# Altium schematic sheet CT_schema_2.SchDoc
size 362 x 192 mm
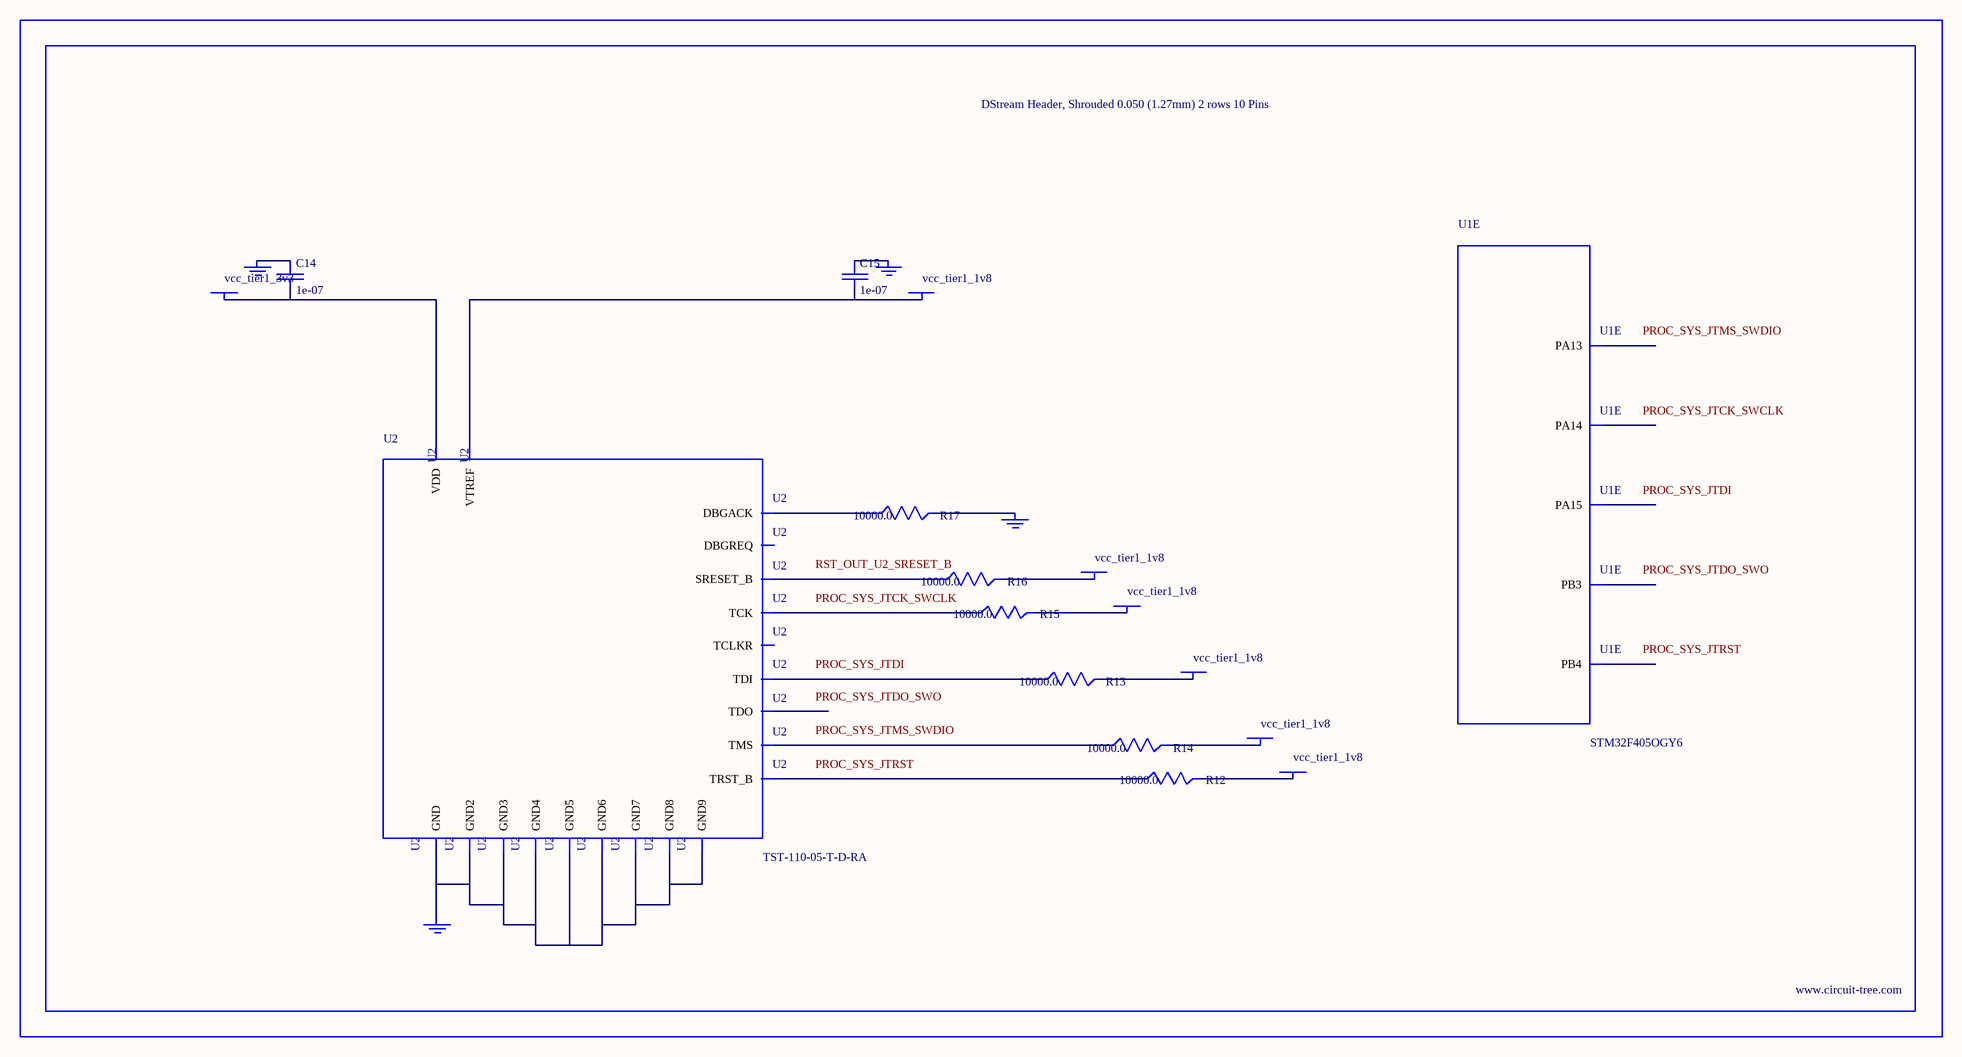
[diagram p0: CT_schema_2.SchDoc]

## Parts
BORDER1  (no value)
C14  1e-07  [C0402]
C15  1e-07  [C0402]
GND_INSTANCE_1_0  (no value)
GND_INSTANCE_1_1  (no value)
GND_INSTANCE_1_2  (no value)
GND_INSTANCE_1_3  (no value)
POWER_INSTANCE_1_0  vcc_tier1_1v8
POWER_INSTANCE_1_1  vcc_tier1_3v3
POWER_INSTANCE_1_2  vcc_tier1_1v8
POWER_INSTANCE_1_3  vcc_tier1_1v8
POWER_INSTANCE_1_4  vcc_tier1_1v8
POWER_INSTANCE_1_5  vcc_tier1_1v8
POWER_INSTANCE_1_6  vcc_tier1_1v8
R12  10000.0  [R0603]
R13  10000.0  [R0603]
R14  10000.0  [R0603]
R15  10000.0  [R0603]
R16  10000.0  [R0603]
R17  10000.0  [R0603]
U1  STM32F405OGY6  [WLCSP90]  (part E of 9)
U2  TST-110-05-T-D-RA  [TST-110-05-T-D-RA]

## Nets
NetC14_1: C14.1 GND_INSTANCE_1_1.0(GND)
NetC14_2: C14.2 POWER_INSTANCE_1_1.0(PWR) U2.2(VDD)
NetC15_1: C15.1 GND_INSTANCE_1_0.0(GND)
NetC15_2: C15.2 POWER_INSTANCE_1_0.0(PWR) U2.1(VTREF)
NetGND_INSTANCE_1_2_0: GND_INSTANCE_1_2.0(GND) R17.2
NetGND_INSTANCE_1_3_0: GND_INSTANCE_1_3.0(GND) U2.4(GND) U2.6(GND2) U2.8(GND3) U2.10(GND4) U2.12(GND5) U2.14(GND6) U2.16(GND7) U2.18(GND8) U2.20(GND9)
NetPOWER_INSTANCE_1_2_0: POWER_INSTANCE_1_2.0(PWR) R12.2
NetPOWER_INSTANCE_1_3_0: POWER_INSTANCE_1_3.0(PWR) R13.2
NetPOWER_INSTANCE_1_4_0: POWER_INSTANCE_1_4.0(PWR) R14.2
NetPOWER_INSTANCE_1_5_0: POWER_INSTANCE_1_5.0(PWR) R15.2
NetPOWER_INSTANCE_1_6_0: POWER_INSTANCE_1_6.0(PWR) R16.2
NetR12_1: R12.1 U2.3(TRST_B)
NetR13_1: R13.1 U2.5(TDI)
NetR14_1: R14.1 U2.7(TMS)
NetR15_1: R15.1 U2.9(TCK)
NetR16_1: R16.1 U2.15(SRESET_B)
NetR17_1: R17.1 U2.19(DBGACK)

Not connected (* = marked no-connect by the designer): U1 A2(PA14) A6(PB4) B3(PA15) B6(PB3) D4(PA13); U2 11(TCLKR) 13(TDO) 17(DBGREQ)

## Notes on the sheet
- Labels drawn without touching a wire or pin: PROC_SYS_JTCK_SWCLK, PROC_SYS_JTDI, PROC_SYS_JTDO_SWO, PROC_SYS_JTMS_SWDIO, PROC_SYS_JTRST, RST_OUT_U2_SRESET_B

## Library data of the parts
BORDER1 = BORDER_PAGE1
C14 C15 = C0402C104K3RACTU
GND_INSTANCE_1_0-GND_INSTANCE_1_3 = GND
POWER_INSTANCE_1_0-POWER_INSTANCE_1_6 = PWR
R12-R17 = RC0603JR-0710KL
